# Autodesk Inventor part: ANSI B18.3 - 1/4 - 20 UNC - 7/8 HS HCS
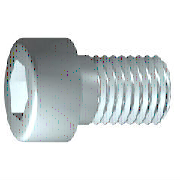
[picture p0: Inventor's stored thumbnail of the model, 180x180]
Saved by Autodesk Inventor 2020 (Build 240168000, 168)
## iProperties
Created: 2008-01
Part Number: ANSI B18.3 - 1/4 - 20 UNC - 7/8 HS HCS
Material: Steel, Mild
Description: Hexagon Socket Head Cap Screw
Document SubType Name: Modeling
Standard: ANSI B18.3
Designer: latalom
Standard Revision: 2003
Standards Organization: ANSI
Language: en-US
Size Designation: 1/4 - 20 UNC - 7/8
Categories: <MemberInstance><Categories><Category DisplayName="Fasteners" InternalName="e4da775c-781d-43d5-af7c-5136215cf5a6" Mnemonic="FSTN"><Category DisplayName="Bolts"
Density: 7.85 g/cm^3
Mass: 8.44809 g
Surface Area: 8.12272 cm^2
Volume: 1.07619 cm^3
Appearance: Steel
IsCustomPart: 0
Author: latalom
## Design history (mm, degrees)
sketch "Sketch1"
  geometry: L1 (-1.71, 0)-(22.225, 0); L2 (22.225, 0)-(22.225, 3.175); L3 (22.225, 3.175)-(3.175, 3.175); L4 (3.175, 3.175)-(0, 3.175); L5 (0, 3.175)-(0, 3.175); L6 (0, 3.175)-(0, 4.763); L7 (0, 4.763)-(-6.35, 4.763); L8 (-6.35, 4.763)-(-6.35, 2.757); L9 (-6.35, 2.757)-(-3.302, 2.757); L10 (-3.302, 2.757)-(-1.71, 0); L11 (-12.065, 0)-(27.94, 0) reference; L12 (0, -0.953)-(0, 5.715) reference; L13 (3.175, 3.175)-(0, 3.175)
  constraints: 22 end point, 6 parallel, 2 collinear, 2 perpendicular, 1 horizontal, 1 point on line
  dimensions: "d1" = 19.0498 distance from line of L3.end L2 (= GEL); "d2" = 3.1751 distance of L4.end L3.end (computed from GAL); "d3" = 6.35 distance between parallel lines of L8 L6 (= KOH); "d4" = 3.048 distance of L8.end L9.end (= INTI); "d5" = 60 deg angle of L10 L1; "d6" = 6.35 diameter of L3 L1 (= GD); "d7" = 6.35 diameter of L5 L1 (= BDM); "d8" = 5.51393 diameter of L9 L1 (= 1.1547 x SW); "d9" = 9.525 diameter of L7 L1 (= KOD); "d26" = 22.225 distance between parallel lines of L12 L2 (= NLG)
revolve "Body" sketch "Sketch1" stored, may be unused: angle "d10" = 90 deg
sketch "Sketch2"
  geometry: L1 (0, -6.668)-(0, 6.668) reference; L2 (-6.668, 0)-(6.668, 0) reference; L3 (2.757, 0)-(1.378, -2.388); L4 (1.378, -2.388)-(-1.378, -2.388); L5 (-1.378, -2.388)-(-2.757, 0); L6 (-2.757, 0)-(-1.378, 2.388); L7 (-1.378, 2.388)-(1.378, 2.388); L8 (1.378, 2.388)-(2.757, 0); 2 further points
  constraints: 12 end point, 1 coincident, 1 horizontal alignment, 1 point on line, 12 other
extrude "Slot" join sketch "Sketch2" stored distance "d11" = 10; taper "d12" = 0 deg
workplane "Work Plane1"
fillet "Fillet2" dims "d30" = 0.1778 (= R)
body "Solid1"
fillet "Fillet1" dims "d17" = 0.635 (= RR)
feature "Thread" dims "d13" = 19.0498 (= GEL), "d14" = 0
chamfer "Chamfer1" distance "d15" = 0.75565 (= -0.5 x SPD + 0.5 x GD); stored, may be unused: second distance "d16" = 0.75565 (= GUL), angle "d27" = 45 deg
other parameters: "GD" = 6.35 (= KOH) [user parameter; used in 2 equation terms], "NLG" = 22.225 [user parameter; used in 1 equation term], "GEL" = 19.0498 [user parameter; used in 2 equation terms], "KOD" = 9.525 [user parameter; used in 1 equation term], "KOH" = 6.35 [user parameter; used in 3 equation terms], "INTI" = 3.048 [user parameter; used in 1 equation term], "GAL" = 3.175 [user parameter; used in 1 equation term], "GUL" = 0.75565 [user parameter; used in 1 equation term], "BDM" = 6.35 (= KOH) [user parameter; used in 1 equation term], "SW" = 4.7752 [user parameter; used in 2 equation terms], "RR" = 0.635 [user parameter; used in 1 equation term], "SPD" = 4.8387 [user parameter; used in 2 equation terms], "d19" = 0, "d28" = 0, "d29" = 0, "R" = 0.1778 [user parameter; used in 1 equation term], "PHH" = 0.2032 [user parameter], "GD1" = 4.8387 (= SPD) [user parameter], "THREADDIA" = 6.35 [user parameter], "FAWI" = 45 deg [user parameter], "PTC" = 1.27 (computed from TPU) [user parameter], "KOH1" = 5.715 [user parameter], "NND" = 6.35 [user parameter], "TOA" = 30 deg [user parameter], "E0" = 5.51536 (= 1.155 x SW) [user parameter]
